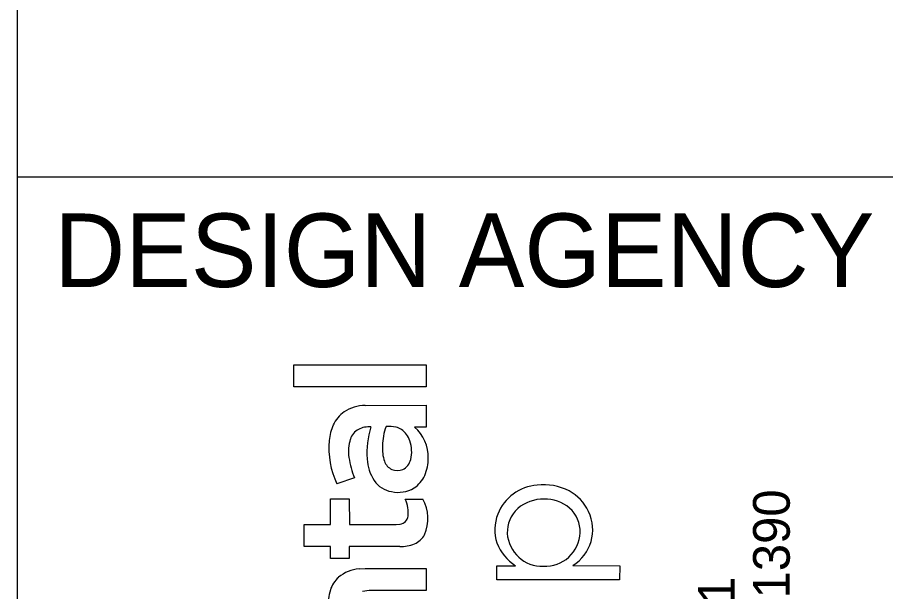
# Model space of a CAD drawing. Extents: x -4.5 to 34, y -0.4 to 22.
# Drawn here: x 32 to 33.18, y 4.436 to 5.217 of the extents above; entities that cross this region are included whole.
import ezdxf

# ---------------------------------------------------------------- set-up
doc = ezdxf.new("R2010")
doc.units = 0
doc.layers.add('SH_Border', color=7, linetype='Continuous')
doc.layers.add('SH_Data', color=7, linetype='Continuous')

msp = doc.modelspace()

# ---------------------------------------------------------------- linework, layer by layer
at = {"layer": 'SH_Border'}
for p, q in [((32, 0.5), (32, 21.5)), ((32, 5), (33.5, 5))]:
    msp.add_line(p, q, dxfattribs=at)
at = {"layer": 'SH_Data'}
for p, q in [((32.3756, 4.7141), (32.3756, 4.744)), ((32.3756, 4.744), (32.5557, 4.744)), ((32.5557, 4.744), (32.5557, 4.7141)), ((32.5557, 4.7141), (32.3756, 4.7141)), ((32.4727, 4.689), (32.5555, 4.6892)), ((32.5555, 4.6892), (32.5557, 4.6596)), ((32.5557, 4.6596), (32.5397, 4.6596)), ((32.4582, 4.5904), (32.4343, 4.5823)), ((32.4254, 4.527), (32.4255, 4.5621)), ((32.4255, 4.5621), (32.4511, 4.5621)), ((32.4511, 4.5621), (32.4512, 4.527)), ((32.527, 4.5616), (32.5511, 4.5616)), ((32.3896, 4.4972), (32.3896, 4.527)), ((32.3896, 4.527), (32.4254, 4.527)), ((32.4512, 4.527), (32.515, 4.527)), ((32.515, 4.527), (32.52, 4.5275)), ((32.4254, 4.4972), (32.3896, 4.4972)), ((32.4254, 4.4807), (32.4254, 4.4972)), ((32.5197, 4.4972), (32.4511, 4.4972)), ((32.4511, 4.4972), (32.4511, 4.4807)), ((32.4511, 4.4807), (32.4254, 4.4807)), ((32.4644, 4.4669), (32.4729, 4.4673)), ((32.4729, 4.4673), (32.5557, 4.4673)), ((32.5557, 4.4673), (32.5557, 4.4375)), ((32.6515, 4.4521), (32.6515, 4.4711)), ((32.6515, 4.4711), (32.6771, 4.4711)), ((32.7549, 4.4713), (32.8186, 4.4711)), ((32.8186, 4.4711), (32.8184, 4.4521)), ((32.8184, 4.4521), (32.6515, 4.4521)), ((32.5557, 4.4375), (32.4814, 4.4375))]:
    msp.add_line(p, q, dxfattribs=at)
msp.add_lwpolyline([(32.3756, 4.7141), (32.3756, 4.744), (32.5557, 4.744), (32.5557, 4.7141)], close=True, dxfattribs=at)
for points in [[(32.4727, 4.689), (32.5555, 4.6892), (32.5557, 4.6596)], [(32.5557, 4.6596), (32.5397, 4.6596)], [(32.4582, 4.5904), (32.4343, 4.5823)], [(32.5197, 4.4972), (32.4511, 4.4972), (32.4511, 4.4807), (32.4254, 4.4807), (32.4254, 4.4972), (32.3896, 4.4972), (32.3896, 4.527), (32.4254, 4.527), (32.4255, 4.5621), (32.4511, 4.5621), (32.4512, 4.527), (32.515, 4.527), (32.52, 4.5275)], [(32.527, 4.5616), (32.5511, 4.5616)], [(32.4644, 4.4669), (32.4729, 4.4673), (32.5557, 4.4673), (32.5557, 4.4375), (32.4814, 4.4375)], [(32.7549, 4.4713), (32.8186, 4.4711), (32.8184, 4.4521), (32.6515, 4.4521)], [(32.6515, 4.4521), (32.6515, 4.4711), (32.6771, 4.4711)]]:
    msp.add_lwpolyline(points, dxfattribs=at)
for centre, radius, start, end in [((32.4745, 4.6326), 0.0565, 91.8942, 122.6317), ((32.4745, 4.6326), 0.0565, 91.8942, 122.6317), ((32.4685, 4.6447), 0.043, 124.537, 155.6594), ((32.4685, 4.6447), 0.043, 124.537, 155.6594), ((32.4882, 4.6361), 0.0646, 155.9764, 175.3149), ((32.4882, 4.6361), 0.0646, 155.9764, 175.3149), ((32.4753, 4.6356), 0.024, 119.4252, 161.6629), ((32.4753, 4.6356), 0.024, 119.4252, 161.6629), ((32.4779, 4.6278), 0.0321, 85.3802, 116.6222), ((32.4779, 4.6278), 0.0321, 85.3802, 116.6222), ((32.5879, 4.6251), 0.1129, 162.0821, 184.5285), ((32.5879, 4.6251), 0.1129, 162.0821, 184.5285), ((32.5801, 4.6313), 0.0841, 159.8366, 178.0362), ((32.5801, 4.6313), 0.0841, 159.8366, 178.0362), ((32.5051, 4.6074), 0.053, 79.6696, 94.2322), ((32.5051, 4.6074), 0.053, 79.6696, 94.2322), ((32.5089, 4.6364), 0.0238, 56.8913, 76.2149), ((32.5089, 4.6364), 0.0238, 56.8913, 76.2149), ((32.5052, 4.6318), 0.0297, 17.5984, 55.7282), ((32.5052, 4.6318), 0.0297, 17.5984, 55.7282), ((32.5055, 4.6191), 0.0529, 358.0746, 49.762), ((32.5055, 4.6191), 0.0529, 358.0746, 49.762), ((32.5364, 4.6308), 0.113, 174.6101, 205.3899), ((32.5364, 4.6308), 0.113, 174.6101, 205.3899), ((32.5076, 4.6265), 0.0576, 163.1369, 188.1675), ((32.5076, 4.6265), 0.0576, 163.1369, 188.1675), ((32.4916, 4.6264), 0.0443, 345.9408, 18.9919), ((32.4916, 4.6264), 0.0443, 345.9408, 18.9919), ((32.5466, 4.6303), 0.0506, 175.5903, 199.8857), ((32.5466, 4.6303), 0.0506, 175.5903, 199.8857), ((32.5473, 4.6297), 0.0973, 186.7598, 203.7981), ((32.5473, 4.6297), 0.0973, 186.7598, 203.7981), ((32.5328, 4.6187), 0.0575, 182.5676, 213.7144), ((32.5328, 4.6187), 0.0575, 182.5676, 213.7144), ((32.5152, 4.6199), 0.0199, 295.2883, 347.4639), ((32.5152, 4.6199), 0.0199, 295.2883, 347.4639), ((32.5019, 4.6168), 0.0566, 336.016, 0.5951), ((32.5019, 4.6168), 0.0566, 336.016, 0.5951), ((32.5164, 4.6189), 0.0184, 198.2844, 293.3081), ((32.5164, 4.6189), 0.0184, 198.2844, 293.3081), ((32.5175, 4.6097), 0.0394, 303.4436, 336.18), ((32.5175, 4.6097), 0.0394, 303.4436, 336.18), ((32.5149, 4.6078), 0.0366, 215.0668, 259.8133), ((32.5149, 4.6078), 0.0366, 215.0668, 259.8133), ((32.7108, 4.5182), 0.0624, 93.9866, 158.3119), ((32.7108, 4.5182), 0.0624, 93.9866, 158.3119), ((32.7156, 4.5065), 0.0746, 62.6889, 97.0135), ((32.7156, 4.5065), 0.0746, 62.6889, 97.0135), ((32.5175, 4.6131), 0.0423, 257.5256, 300.882), ((32.5175, 4.6131), 0.0423, 257.5256, 300.882), ((32.7212, 4.5191), 0.0608, 25.0657, 61.9602), ((32.7212, 4.5191), 0.0608, 25.0657, 61.9602), ((32.4863, 4.542), 0.0452, 10.1545, 25.723), ((32.4863, 4.542), 0.0452, 10.1545, 25.723), ((32.503, 4.5351), 0.0549, 336.589, 28.8991), ((32.503, 4.5351), 0.0549, 336.589, 28.8991), ((32.7138, 4.5102), 0.0513, 87.8965, 131.1812), ((32.7138, 4.5102), 0.0513, 87.8965, 131.1812), ((32.7175, 4.5102), 0.0513, 49.9089, 92.0363), ((32.7175, 4.5102), 0.0513, 49.9089, 92.0363), ((32.4957, 4.5436), 0.0356, 351.914, 10.2059), ((32.4957, 4.5436), 0.0356, 351.914, 10.2059), ((32.7092, 4.5167), 0.0434, 132.3289, 182.0949), ((32.7092, 4.5167), 0.0434, 132.3289, 182.0949), ((32.7215, 4.5173), 0.0433, 358.0487, 47.9447), ((32.7215, 4.5173), 0.0433, 358.0487, 47.9447), ((32.7245, 4.52), 0.0574, 301.9776, 25.6418), ((32.7245, 4.52), 0.0574, 301.9776, 25.6418), ((32.5184, 4.54), 0.0126, 277.6142, 353.7918), ((32.5184, 4.54), 0.0126, 277.6142, 353.7918), ((32.707, 4.5202), 0.0581, 158.656, 198.171), ((32.707, 4.5202), 0.0581, 158.656, 198.171), ((32.5291, 4.5261), 0.0275, 292.6889, 332.0598), ((32.5291, 4.5261), 0.0275, 292.6889, 332.0598), ((32.7135, 4.5181), 0.0478, 183.5974, 271.7045), ((32.7135, 4.5181), 0.0478, 183.5974, 271.7045), ((32.7172, 4.518), 0.0477, 267.3149, 357.4019), ((32.7172, 4.518), 0.0477, 267.3149, 357.4019), ((32.5209, 4.5486), 0.0514, 268.6727, 291.5235), ((32.5209, 4.5486), 0.0514, 268.6727, 291.5235), ((32.7103, 4.5243), 0.0627, 200.8399, 238.0162), ((32.7103, 4.5243), 0.0627, 200.8399, 238.0162), ((32.4687, 4.4172), 0.0499, 94.9706, 130.2248), ((32.4687, 4.4172), 0.0499, 94.9706, 130.2248), ((32.4635, 4.4255), 0.0402, 132.2238, 161.6823), ((32.4635, 4.4255), 0.0402, 132.2238, 161.6823), ((32.4787, 4.4211), 0.056, 162.274, 187.7917), ((32.4787, 4.4211), 0.056, 162.274, 187.7917), ((32.4811, 4.3915), 0.046, 89.6051, 105.3303), ((32.4811, 4.3915), 0.046, 89.6051, 105.3303)]:
    msp.add_arc(centre, radius, start, end, dxfattribs=at)

# ---------------------------------------------------------------- texts
msp.add_text('DESIGN AGENCY', height=0.1, dxfattribs=at).set_placement((32.05, 4.85))
for s, p in [('800.835.1390', (33.0497, 4.1671)), ('450 GRANT ST., AKRON, OH  44311', (32.9749, 3.3374))]:
    msp.add_text(s, height=0.049846, rotation=90, dxfattribs=at).set_placement(p)

doc.saveas('drawing.dxf')
